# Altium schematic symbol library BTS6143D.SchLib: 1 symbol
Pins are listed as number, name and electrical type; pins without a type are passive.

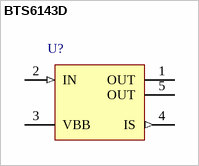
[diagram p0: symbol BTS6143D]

## BTS6143D
designator U?
PROFET Smart Highside Power Switch, 1 Channel, 10 A Load Current, -40 to 150 degC, PG-TO252-5-11, Reel, Green; Manufacturer: Infineon; PartNumber: BTS6143D; Channels: 1; Green: TRUE; Group: Automotive Qualified; Load Current (typ): 10 A; Ptot (max): 59 W; Recommended Operating Voltage Max.: 38 V; Recommended Operating Voltage Min.: 5.5 V; RON @ 25degreesC: 10 mOhm; RON(max) @ 150degreesC: 18 mOhm; toff (max): 500 us
footprint INF-PG-TO252-5-11_N (DPAK, 5-Leads, Body 6.5x6.12mm, Pitch 1.14mm, IPC Medium Density)
footprint INF-PG-TO252-5-11_L (DPAK, 5-Leads, Body 6.5x6.12mm, Pitch 1.14mm, IPC High Density)
footprint INF-PG-TO252-5-11_M (DPAK, 5-Leads, Body 6.5x6.12mm, Pitch 1.14mm, IPC Low Density)
pins: 1 OUT (hiz) "Output; output to the load; pin 1 and 5 must be externally shorted.", 2 IN (in) "Input; activates the power switch if shorted to ground.", 3 VBB (power) "Supply Voltage; positive power supply voltage; tab and pin 3 are internally shorted.", 4 IS (out) "Sense Output; Diagnostic feedback; provides at normal operation a sense current proportional to the load current; in case of overload, overtemperature and/or short circuit a defined current is provided.", 5 OUT (hiz) "Output; output to the load; pin 1 and 5 must be externally shorted."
